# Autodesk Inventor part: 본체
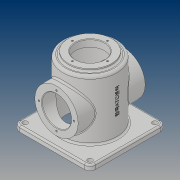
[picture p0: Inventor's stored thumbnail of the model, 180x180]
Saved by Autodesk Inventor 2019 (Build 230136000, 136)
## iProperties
Created: 2019-03
Part Number: 본체
Material: 일반
Document SubType Name: Modeling
Designer: PC312-18
Density: 1 g/cm^3
Appearance: 기본값
Mass: 414.937 g
Surface Area: 1160.05 cm^2
Volume: 414.937 cm^3
Author: PC312-18
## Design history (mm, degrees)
sketch "스케치1"
  geometry: L1 (0, 0)-(120, 0); L2 (120, 0)-(120, 50); L3 (120, 50)-(0, 50); L4 (0, 50)-(0, 0)
  constraints: 8 end point, 2 horizontal, 2 vertical
  dimensions: "d0" = 120 distance of L1.start L1.end; "d1" = 100 diameter of L3 L1
revolve "회전1" sketch "스케치1" stored, may be unused: angle "d2" = 90 deg
sketch "스케치2"
  geometry: L1 (0, 0)-(112, 0); L2 (112, 0)-(112, 45); L3 (112, 45)-(0, 45); L4 (0, -50)-(0, 50) reference; L5 (0, 0)-(0, 45)
  constraints: 8 end point, 2 horizontal, 2 vertical, 1 point on line
  dimensions: "d3" = 112 distance of L1.start L1.end; "d4" = 90 diameter of L3 L1
revolve "회전2" sketch "스케치2" stored, may be unused: angle "d5" = 90 deg
fillet "모깎기1" dims "d6" = 5
fillet "모깎기2" dims "d7" = 3
sketch "스케치3"
  geometry: L1 (-70, -70)-(70, -70); L2 (70, -70)-(70, 70); L3 (70, 70)-(-70, 70); L4 (-70, 70)-(-70, -70); L5 (-70, -70)-(70, 70); L6 (70, -70)-(-70, 70); C1 r 45 at (0, 0) reference; C2 r 50 at (0, 0) reference; 1 further point
  constraints: 12 end point, 2 midpoint, 2 parallel, 1 horizontal, 1 perpendicular
  dimensions: "d8" = 140 distance of L3.end L2.end; "d9" = 140 distance of L2.end L1.end
extrude "돌출1" join sketch "스케치3" distance "d10" = 10; taper "d11" = 0 deg
node "작업 평면1"
sketch "스케치4"
  geometry: C1 r 40 at (0, 0); 1 further point
  constraints: 1 centre point, 1 coincident
  dimensions: "d13" = 80 diameter of C1
extrude "돌출2" join sketch "스케치4" stored distance "d14" = 10; taper "d15" = 0 deg
sketch "스케치5"
  geometry: C1 r 27 at (0, 0); 1 further point
  constraints: 1 centre point, 1 coincident
  dimensions: "d16" = 54 diameter of C1
extrude "돌출3" cut sketch "스케치5" extent not by distance; stored distance "d17" = 10; taper "d18" = 0 deg
node "작업 평면2"
sketch "스케치6"
  geometry: L1 (70, 0)-(-70, 0) reference; C1 r 40 at (0, 60); 2 further points
  constraints: 1 centre point, 1 midpoint, 1 vertical alignment
  dimensions: "d20" = 80 diameter of C1; "d21" = 60 distance from line of L1 C1.centre
extrude "돌출4" join sketch "스케치6" stored distance "d22" = 10; taper "d23" = 0 deg
sketch "스케치7"
  geometry: L1 (70, -60)-(-70, -60) reference; C1 r 40 at (0, 0) reference; 3 further points
  constraints: 1 midpoint, 1 vertical alignment
  dimensions: "d24" = 32.5 distance of C1.centre point (0, 32.5)
hole "구멍1" sketch "스케치7" at (0, 32.5) diameter "d25" = 3.242; stored, may be unused: countersink angle "d29" = 90 deg, drill point angle "d31" = 118 deg; dims "d26" = 8, "d27" = 4, "d28" = 2, "d30" = 10
sketch "스케치8"
  geometry: C1 r 27 at (0, 0); C2 r 40 at (0, 0) reference; 1 further point
  constraints: 1 centre point, 1 concentric
  dimensions: "d35" = 54 diameter of C1
extrude "돌출5" cut sketch "스케치8" extent not by distance; stored distance "d36" = 10; taper "d37" = 0 deg
sketch "스케치9"
  geometry: 2 further points
  constraints: 1 vertical alignment
  dimensions: "d38" = 32.5 distance of point (0, 0) point (0, 32.5)
hole "구멍2" sketch "스케치9" at (0, 32.5) diameter "d39" = 3.242; stored, may be unused: countersink angle "d43" = 90 deg, drill point angle "d45" = 118 deg; dims "d40" = 8, "d41" = 4, "d42" = 2, "d44" = 10
fillet "모깎기3" dims "d49" = 10
chamfer "모따기1" distance "d50" = 1; stored, may be unused: second distance "d51" = 2, angle "d52" = 45 deg
sketch "스케치10"
  geometry: A1 r 10 centre (60, -60) between (60, -70) and (70, -60) reference; A2 r 10 centre (60, 60) between (70, 60) and (60, 70) reference; A3 r 10 centre (-60, -60) between (-70, -60) and (-60, -70) reference; A4 r 10 centre (-60, 60) between (-60, 70) and (-70, 60) reference; 5 further points
  constraints: 4 coincident
hole "구멍3" sketch "스케치10" at (60, -60), (60, 60), (-60, -60), (-60, 60) diameter "d53" = 9; stored, may be unused: countersink angle "d57" = 90 deg, drill point angle "d59" = 118 deg; dims "d54" = 8, "d55" = 4, "d56" = 2, "d58" = 10
fillet "모깎기4" dims "d60" = 3
fillet "모깎기5" dims "d61" = 3
node "작업 평면3"
sketch "스케치11"
  geometry: L1 (0, -60)-(0, 60) reference; 3 further points
  constraints: 1 horizontal alignment, 1 midpoint, 1 other
  dimensions: "d63" = 70 distance from line of L1 point (70, 0)
feature "엠보싱1" sketch "스케치11" dims "d0" = 120, "d1" = 100, "d64" = 0.5, "d65" = 0
node "솔리드1"
pattern_circular "원형 패턴1" dims angle "d33" = 360 deg
mirror "미러1"
pattern_circular "원형 패턴2" dims angle "d47" = 360 deg
node "투영된 루프1"
other parameters: "d12" = 125, "d19" = 62
